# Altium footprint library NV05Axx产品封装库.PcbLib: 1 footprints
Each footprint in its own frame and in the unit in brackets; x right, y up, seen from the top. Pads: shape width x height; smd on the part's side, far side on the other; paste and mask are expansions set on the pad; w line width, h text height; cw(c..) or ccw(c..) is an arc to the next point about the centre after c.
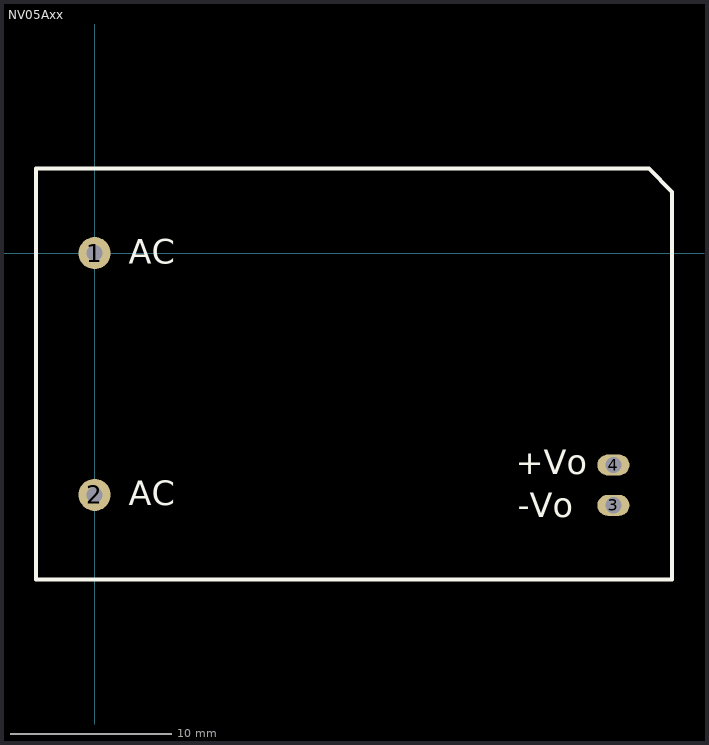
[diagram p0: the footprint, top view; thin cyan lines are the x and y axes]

## NV05Axx [mm]
pads (4):
  round 2 hole 1: 1(0,0) 2(0,-15)
  oval 2x1.3 hole 1: 3(32.2,-15.65) 4(32.2,-13.15)
Top Overlay:
  lines w0.254: -3.65,-20.25 35.85,-20.25 35.85,3.803 34.403,5.25 -3.65,5.25 -3.65,-20.25
  text "+Vo" at 26.133,-13.723 h1.52
  text "-Vo" at 26.26,-16.39 h1.52
  text "AC" at 2.13,-15.642 h1.52
  text "AC" at 2.13,-0.642 h1.52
